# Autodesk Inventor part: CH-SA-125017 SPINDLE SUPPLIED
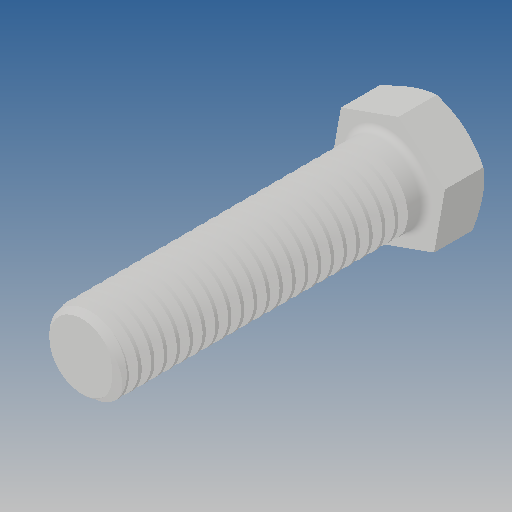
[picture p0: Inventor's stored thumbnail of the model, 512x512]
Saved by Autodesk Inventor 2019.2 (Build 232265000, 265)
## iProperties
Created: 2015-08
Part Number: CH-SA-125017 SPINDLE SUPPLIED
Material: Ogólny
Document SubType Name: Modeling
Designer: CADENGINEERING4
Density: 1 g/cm^3
Appearance: Domyślna
Author: CADENGINEERING4
Revision Number: ÈÎºÎ
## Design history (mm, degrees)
feature "ÇÐ³ý-É¨Ãè3"
node "Bryła1"
